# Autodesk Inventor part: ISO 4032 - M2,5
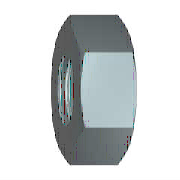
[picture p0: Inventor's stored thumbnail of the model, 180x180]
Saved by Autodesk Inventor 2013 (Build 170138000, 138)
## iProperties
Created: 2012-02
Part Number: ISO 4032 - M2,5
Material: Edelstahl, 440C
Description: Sechskantmuttern, Typ 1 - Produktklasse A und B
Document SubType Name: Modeling
Standard: ISO 4032
Designer: rYan
Standard Revision: Third edition 1999-08-15
Standards Organization: ISO
Language: de-DE
Size Designation: M2,5
Categories: <MemberInstance><Categories><Category DisplayName="Verbindungselemente" InternalName="e4da775c-781d-43d5-af7c-5136215cf5a6" Mnemonic="FSTN"><Category DisplayNam
Density: 7.75 g/cm^3
IsCustomPart: 0
Author: rYan
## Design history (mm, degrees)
sketch "Skizze1"
  geometry: L1 (-2.887, 0)-(-1.443, 2.5); L2 (-1.443, 2.5)-(1.443, 2.5); L3 (1.443, 2.5)-(2.887, 0); L4 (2.887, 0)-(1.443, -2.5); L5 (1.443, -2.5)-(-1.443, -2.5); L6 (-1.443, -2.5)-(-2.887, 0); 2 further points
  constraints: 12 end point, 1 coincident, 1 horizontal, 11 other
  dimensions: "d0" = 5.7735 distance of L3.end L1.start (= 1.1547 x SW)
extrude "Körper" new body sketch "Skizze1" distance "d1" = 2 (= KOH); taper "d2" = 0 deg
sketch "Skizze2"
  geometry: L1 (0, 1.443)-(0, 2.887) reference; L2 (0, 2.887)-(2, 2.887) reference; L3 (2, 1.443)-(2, 2.887) reference; L4 (-0.4, 0)-(2.4, 0) reference; L5 (0.483, 2.887)-(0, 2.05); L6 (1.517, 2.887)-(2, 2.05)
  constraints: 4 end point, 4 point on line
  dimensions: "d3" = 30 deg angle of L1 L5 (= ANG1); "d4" = 30 deg angle of L3 L6 (= ANG2); "d5" = 4.1 diameter of L5.end L4 (= SW0); "d6" = 4.1 diameter of L6.end L4 (= SW01)
revolve "Fase1" sketch "Skizze2" stored, may be unused: angle "d7" = 90 deg
sketch "Skizze3"
  geometry: 4 further points
  constraints: 1 coincident, 1 other
hole "Gewinde" sketch "Skizze3" at (0, 0) diameter "d25" = 2.013; stored, may be unused: countersink angle "d29" = 82 deg, drill point angle "d31" = 118 deg; dims "d26" = 6, "d27" = 4, "d28" = 2, "d30" = 8
workaxis "Work Axis1"
workplane "Work Plane1"
body "Solid1"
chamfer "Fase2" distance "d8" = 0.24357 (= -0.5 x GD1 + 0.5 x NND); stored, may be unused: angle "d9" = 30 deg, second distance "d40" = 0.24357 (= -0.5 x GD1 + 0.5 x NND)
chamfer "Fase3" distance "d10" = 0.24357 (= -0.5 x GD1 + 0.5 x NND); stored, may be unused: angle "d11" = 30 deg, second distance "d41" = 0.24357 (= -0.5 x GD1 + 0.5 x NND)
other parameters: "ANG1" = 30 deg [user parameter; used in 1 equation term], "ANG2" = 30 deg [user parameter; used in 1 equation term], "NND" = 2.5 [user parameter; used in 4 equation terms], "KOH" = 2 [user parameter; used in 1 equation term], "SW" = 5 [user parameter; used in 2 equation terms], "SW0" = 4.1 [user parameter; used in 2 equation terms], "SW01" = 4.1 (= SW0) [user parameter; used in 1 equation term], "GD1" = 2.01286 (computed from THREADDIA, PTC, TOA) [user parameter; used in 4 equation terms], "d13" = 0, "d14" = 0, "d39" = 0, "d42" = 0, "GUL" = 0.24357 (= 0.541266 x PTC) [user parameter], "TPU" = 22.22222 (computed from PTC) [user parameter], "THREADDIA" = 2.5 [user parameter; used in 1 equation term], "TOA" = 30 deg [user parameter; used in 1 equation term], "PTC" = 0.45 [user parameter; used in 4 equation terms], "E0" = 5.775 (= 1.155 x SW) [user parameter], "GAL" = 0.24357 (= 0.541266 x PTC) [user parameter]
